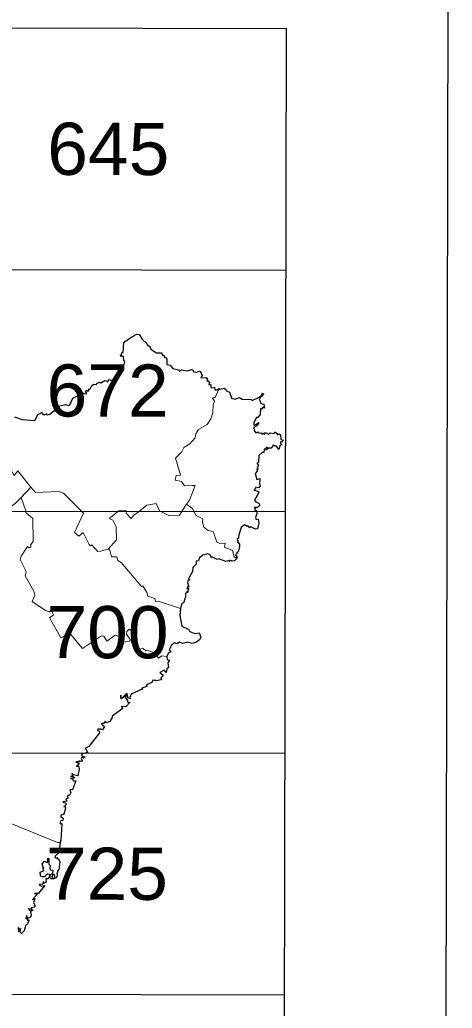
# Model space of a CAD drawing. Extents: x 483847 to 488453, y 4383581 to 4386795.
# Drawn here: x 488291.2 to 488453, y 4385556 to 4385925.5 of the extents above; entities that cross this region are included whole.
import ezdxf
from ezdxf.enums import TextEntityAlignment as Align

# ---------------------------------------------------------------- set-up
doc = ezdxf.new("R2010")
doc.units = 0
doc.header["$LTSCALE"] = 3.8
doc.header["$PDMODE"] = 32
doc.header["$PDSIZE"] = 1.9
doc.linetypes.add('DOTTED', pattern=[1.5, 0.3, -1.2])
for name, color, linetype, lineweight in [('1', 7, 'Continuous', 13), ('2', 7, 'DOTTED', 13), ('3', 7, 'Continuous', 25)]:
    doc.layers.add(name, color=color, linetype=linetype, lineweight=lineweight)

msp = doc.modelspace()

# ---------------------------------------------------------------- linework, layer by layer
at = {"layer": '1', "lineweight": 25}
for p, q in [((487975.35, 4385923.09), (488391.03, 4385922.3)), ((488390.17, 4385470.67), (488391.03, 4385922.31)), ((487975.18, 4385832.76), (488390.86, 4385831.97)), ((487836.45, 4385742.71), (488390.69, 4385741.65)), ((487836.28, 4385652.38), (488390.51, 4385651.32)), ((487836.1, 4385562.06), (488390.34, 4385561))]:
    msp.add_line(p, q, dxfattribs=at)
msp.add_lwpolyline([(483853.06, 4386794.93), (488453.05, 4386786.19), (488446.96, 4383581.19), (483846.97, 4383589.93)], close=True, dxfattribs=at)
at = {"layer": '3'}
for p, q in [((488364.27, 4385787.18), (488364.98, 4385787.18)), ((488364.98, 4385787.18), (488365.77, 4385787.65)), ((488365.77, 4385787.65), (488365.54, 4385787.18))]:
    msp.add_line(p, q, dxfattribs=at)
at = {"layer": '3', "lineweight": 13}
msp.add_line((488353.57, 4385744.47), (488351.97, 4385741.99), dxfattribs=at)
at = {"layer": '3'}
for points in [[(488330.22, 4385798.06), (488330.02, 4385799.69), (488329.33, 4385799.93), (488329.22, 4385799.57), (488328.89, 4385800.29), (488329.27, 4385800.27), (488329.54, 4385801.24), (488329.95, 4385801.17), (488330.15, 4385805.04), (488333.43, 4385807.07)], [(488333.43, 4385807.07), (488335.04, 4385807.94), (488335.96, 4385807.82), (488337.1, 4385806.06), (488338.83, 4385804.54), (488339.21, 4385803.62), (488339.81, 4385803.58), (488340.28, 4385802.35), (488342.44, 4385801.01), (488344.09, 4385800.99), (488344.78, 4385800.03), (488345.32, 4385800.06), (488345.43, 4385799.2)], [(488345.43, 4385799.2), (488346.04, 4385799.2), (488346.31, 4385798.5), (488346.26, 4385796.7), (488347.5, 4385796.38), (488348.57, 4385795.2), (488350.59, 4385794.66), (488350.99, 4385794.14), (488351.8, 4385794.65), (488353.95, 4385794.3), (488355.55, 4385794.76), (488356.03, 4385794.62), (488356.25, 4385793.91), (488357.43, 4385793.76)], [(488321.34, 4385789.9), (488321.63, 4385789.75), (488323.03, 4385790.62), (488323.77, 4385790.52), (488324.11, 4385790.02), (488324.72, 4385791.07), (488325.34, 4385790.73), (488326.19, 4385790.93), (488326.81, 4385791.84), (488327.82, 4385792.14), (488328.49, 4385792.96), (488328.24, 4385794.64), (488329.71, 4385795.43), (488330.48, 4385797.15), (488330.58, 4385797.78), (488330.22, 4385798.06)], [(488357.43, 4385793.76), (488358.8, 4385794.31), (488359.55, 4385792.56), (488359.01, 4385791.62), (488360.99, 4385791.76), (488361.48, 4385791.09), (488361.22, 4385790.48), (488361.69, 4385790.55), (488362.19, 4385789.97), (488361.96, 4385788.99), (488362.75, 4385789.13), (488362.69, 4385788.03), (488363, 4385787.9), (488364.08, 4385788.15), (488364.27, 4385787.18)], [(488316.94, 4385787.07), (488316.78, 4385786.58), (488316.35, 4385786.89), (488315.77, 4385786.58), (488316.22, 4385785.87), (488315.98, 4385785.56), (488314.88, 4385785.89), (488314.06, 4385785.07), (488313.14, 4385785.42), (488312.97, 4385784.91), (488311, 4385783.89), (488309.67, 4385781.17), (488308.45, 4385781.54)], [(488321.34, 4385789.9), (488319.95, 4385789.48), (488319.79, 4385789.09), (488318.9, 4385789.16), (488317.97, 4385788.38), (488317.41, 4385787.27), (488316.93, 4385787.48), (488316.94, 4385787.07)], [(488365.77, 4385787.65), (488366.08, 4385787.37), (488367.77, 4385787.75), (488368.52, 4385787.2)], [(488368.52, 4385787.2), (488368.64, 4385786.75), (488369.68, 4385786.35), (488370.51, 4385784.08), (488371.78, 4385783.66), (488373.5, 4385784.27), (488374.43, 4385783.74), (488377.81, 4385783.62), (488378.16, 4385783.19), (488380.58, 4385784.27), (488381.68, 4385785.1), (488381.93, 4385785.94), (488382.6, 4385785.63), (488382.05, 4385785.18), (488382.16, 4385784.89)], [(488382.16, 4385784.89), (488381.05, 4385784.28), (488380.96, 4385783.6), (488381.42, 4385782.09), (488382.6, 4385781.83), (488382.77, 4385780.37), (488382.13, 4385780.64), (488381.81, 4385780.01), (488381.33, 4385780.03), (488381.13, 4385777.91), (488380.34, 4385776.85), (488379.87, 4385776.78), (488378.83, 4385774.97), (488378.76, 4385773.78), (488379.38, 4385774.06)], [(488308.45, 4385781.54), (488305.78, 4385780.93), (488306.04, 4385780.68), (488305.14, 4385779.15), (488303.95, 4385779.2), (488302.65, 4385778.06), (488301.53, 4385777.7), (488301.32, 4385778.21), (488300.26, 4385777.68), (488299.93, 4385778.19)], [(488299.93, 4385778.19), (488299.27, 4385778.71), (488299.05, 4385778.2), (488298.03, 4385777.92), (488296.71, 4385775.58), (488292.24, 4385775.99), (488289.37, 4385776.95)], [(488379.38, 4385774.06), (488380.7, 4385774.93), (488379.92, 4385773.71), (488378.79, 4385773.07), (488378.93, 4385771.95), (488379.59, 4385771.04), (488380.6, 4385771.44), (488380.72, 4385770.95), (488381.65, 4385771.07), (488381.79, 4385770.57), (488382.36, 4385770.98), (488382.77, 4385770.59), (488383.14, 4385771.18), (488384.48, 4385770.61), (488384.97, 4385771.09), (488386.4, 4385770.9), (488386.72, 4385771.53), (488387.63, 4385770.77), (488387.54, 4385770.34), (488388.34, 4385770.77)], [(488388.34, 4385770.77), (488388.82, 4385770.4), (488388.96, 4385768.64), (488389.77, 4385768.39), (488389.45, 4385767.64), (488388.75, 4385767.78), (488388.74, 4385767.23), (488389.33, 4385766.69), (488388.51, 4385766.23), (488388.21, 4385764.83), (488387.34, 4385766.12), (488386.69, 4385766.13), (488386.16, 4385766.67), (488385.35, 4385765.43), (488384.46, 4385765.37), (488383.36, 4385764.57), (488383.53, 4385765.14)], [(488383.53, 4385765.14), (488384.25, 4385765.4), (488383.39, 4385765.78), (488383.35, 4385765.22), (488382.68, 4385765.05), (488382.57, 4385763.77), (488381.91, 4385763.73), (488380.72, 4385762.58), (488380.61, 4385759.99), (488380, 4385759.76), (488380.54, 4385759.03), (488380.12, 4385757.85), (488380.42, 4385757.39), (488379.99, 4385757.39), (488380.1, 4385756.78), (488379.34, 4385755.94)], [(488379.34, 4385755.94), (488379.91, 4385753.7), (488381.1, 4385754.01), (488380.92, 4385751.82), (488381.28, 4385751.4), (488380.75, 4385750.57), (488379.51, 4385750.81), (488379.3, 4385750.02), (488378.84, 4385749.84), (488380.72, 4385749.06), (488380.6, 4385748.49)], [(488380.6, 4385748.49), (488379.12, 4385745.88), (488379.6, 4385745.58), (488379.5, 4385745.26), (488380.72, 4385744.84), (488381.01, 4385744.12), (488380.21, 4385743.21), (488378.96, 4385743.22), (488379.3, 4385742.98), (488379.21, 4385742.21), (488379.67, 4385742.05)], [(488379.67, 4385742.05), (488379.97, 4385741.82), (488379.93, 4385740.76), (488379.43, 4385739.5), (488379.72, 4385738.72), (488380.5, 4385738.82), (488380.73, 4385737.35), (488380.22, 4385735.24), (488379.4, 4385735.05), (488377.71, 4385735.92), (488377.13, 4385735.55), (488376.66, 4385736.31), (488376.34, 4385736.06), (488375.29, 4385736.69), (488374.12, 4385735.71), (488373.19, 4385733.01)], [(488373.19, 4385733.01), (488373.04, 4385731.75), (488372.55, 4385731.34), (488373, 4385730.59), (488372.66, 4385730.3), (488373.42, 4385729.42), (488373.42, 4385728.44), (488373.03, 4385726.98), (488372.01, 4385725.5), (488372.59, 4385724.52), (488372.43, 4385724.17)], [(488359.75, 4385725.39), (488358.41, 4385724.23), (488358.09, 4385723.21), (488357.25, 4385723.08), (488357.22, 4385721.99), (488356.04, 4385720.82), (488355.91, 4385719.32), (488354.39, 4385716.55), (488354.92, 4385716.14), (488354.12, 4385715.9), (488353.97, 4385715.13), (488354.45, 4385713.47), (488354.13, 4385713.64), (488353.81, 4385712.93), (488354.59, 4385713.18), (488354.23, 4385712.75), (488354.42, 4385712.47), (488353.96, 4385712.31), (488354.29, 4385711.78), (488353.57, 4385711.69)], [(488372.43, 4385724.17), (488371.53, 4385723.23), (488370.73, 4385723.1), (488369.88, 4385723.51), (488369.7, 4385723.02), (488369.36, 4385723.26), (488368.34, 4385722.97), (488365.74, 4385723.97), (488365.16, 4385723.76), (488363.39, 4385724.61), (488362.94, 4385724.42), (488362.52, 4385725.47), (488361.56, 4385725.89), (488359.75, 4385725.39)], [(488353.57, 4385711.69), (488354.18, 4385711.38), (488353.2, 4385711.11), (488353.27, 4385709.66), (488352.82, 4385708.93), (488353.06, 4385708.76), (488352.46, 4385707.58), (488351.77, 4385707.1), (488351.43, 4385705.45)], [(488351.43, 4385705.45), (488351.13, 4385702.82), (488351.84, 4385698.86), (488354.56, 4385697.56), (488354.82, 4385696.83)], [(488354.82, 4385696.83), (488356.7, 4385696.13), (488358.42, 4385696.39), (488358.98, 4385694.75), (488358.47, 4385693.72), (488357.35, 4385692.86), (488355.7, 4385692.32), (488354.04, 4385692.85), (488352.12, 4385692.4), (488350.99, 4385692.79), (488350.09, 4385692.25)], [(488350.09, 4385692.25), (488349.13, 4385692.56), (488348.04, 4385691.75), (488347.12, 4385689.96), (488347.77, 4385689.14), (488346.95, 4385688.83), (488346.3, 4385687.53)], [(488346.3, 4385687.53), (488346.39, 4385686.42), (488347.3, 4385686.1), (488346.62, 4385685.08), (488346.93, 4385683.41), (488346.3, 4385682.89), (488346.07, 4385681.55), (488345.23, 4385682.43), (488343.71, 4385681.56), (488344.72, 4385680.64), (488344.63, 4385679.96), (488344.02, 4385679.52), (488344.25, 4385678.75), (488342.21, 4385678.42), (488341.81, 4385678.77), (488341.48, 4385678.48), (488341.03, 4385678.67), (488340.66, 4385677.76), (488338.65, 4385676.9), (488338.8, 4385676.23), (488336.93, 4385675.71), (488336.88, 4385675.42), (488337.26, 4385675.43)], [(488337.26, 4385675.43), (488332.93, 4385673.39), (488332.37, 4385672.17), (488332.64, 4385671.67), (488331.77, 4385671.91), (488331.35, 4385673.75), (488329.5, 4385672.09), (488329.11, 4385672.16), (488329.1, 4385673.07), (488328.92, 4385672.08), (488329.35, 4385671.78), (488331.19, 4385673.02), (488330.82, 4385672.09), (488331.59, 4385671.08), (488331.67, 4385670.25), (488332.57, 4385670.44), (488330.95, 4385668.73), (488329.14, 4385668.82)], [(488329.14, 4385668.82), (488329.8, 4385668.05), (488325.81, 4385665.2), (488325.88, 4385664.72), (488324.95, 4385663.24), (488323.75, 4385662.74), (488323.22, 4385663.32), (488322.86, 4385662.44), (488321.96, 4385662.48), (488321.88, 4385662.15), (488322.99, 4385661.32), (488322.17, 4385660.08), (488321.53, 4385660.26)], [(488321.53, 4385660.26), (488320.4, 4385660.31), (488320.33, 4385659.87), (488320.98, 4385659.64), (488321.11, 4385658.93), (488317.1, 4385653.85), (488315.8, 4385653.24), (488316.61, 4385651.58)], [(488316.61, 4385651.58), (488314.29, 4385651.02), (488314.58, 4385650.17), (488315.68, 4385650.02), (488315.07, 4385649.54), (488314.44, 4385649.83), (488314.24, 4385649.35), (488314.63, 4385648.61), (488314.34, 4385648.27), (488313.39, 4385648.47), (488313.61, 4385648.05), (488312.27, 4385648.17), (488313.48, 4385647.49), (488312.78, 4385646.63)], [(488312.78, 4385646.63), (488312.41, 4385646.49), (488313.33, 4385646.37), (488313.53, 4385645.34), (488312.96, 4385642.87), (488311.3, 4385643.25), (488310.79, 4385643.92), (488310.93, 4385642.91), (488310.21, 4385642.58), (488311.25, 4385642.58), (488311.88, 4385642.07), (488310.28, 4385641.77), (488310.91, 4385641.85), (488311.36, 4385641.06), (488312.17, 4385640.99), (488311.53, 4385639.02)], [(488311.53, 4385639.02), (488310.95, 4385637.6), (488309.99, 4385637.76), (488310.35, 4385636.52), (488309.83, 4385635.53), (488309.15, 4385635.49), (488309.28, 4385634.43), (488308.49, 4385634.34), (488308.9, 4385633.36), (488307.37, 4385633.16), (488308.47, 4385632.65), (488308.64, 4385632.15), (488307.73, 4385631.34), (488308.25, 4385631.4), (488308.3, 4385630.85), (488307.78, 4385628.57), (488307.25, 4385628.28)], [(488307.25, 4385628.28), (488306.88, 4385628.37), (488306.48, 4385627.67), (488307.47, 4385627.03), (488307.37, 4385626.22), (488306.6, 4385626.06), (488306.2, 4385625.27), (488306.43, 4385624.83), (488306.87, 4385625.19), (488306.93, 4385624.8), (488306.64, 4385618.82), (488306.32, 4385618.01)], [(488306.32, 4385618.01), (488305.89, 4385614.04), (488304.49, 4385612.83), (488304.43, 4385612.35), (488305.07, 4385612.05), (488305.41, 4385612.33), (488305.34, 4385611.87), (488305.87, 4385611.63), (488306.3, 4385610.72), (488305.84, 4385607.77), (488305.31, 4385607.39), (488305.5, 4385606.98)], [(488298.89, 4385606.41), (488298.94, 4385606.86), (488300.09, 4385607.35), (488300, 4385608.42), (488300.38, 4385608.51), (488300.03, 4385608.61), (488299.6, 4385609.92), (488300.5, 4385610.97), (488301.46, 4385610.44), (488301.79, 4385610.87), (488301.78, 4385612.13), (488302.17, 4385611.95), (488302.07, 4385609.85), (488302.67, 4385609.3), (488302.48, 4385608.18), (488302.65, 4385607.72), (488303.56, 4385607.58), (488303.53, 4385606.41)], [(488298.89, 4385606.41), (488298.87, 4385605.53), (488299.63, 4385605.22), (488300.66, 4385605.2), (488301.67, 4385606.25), (488302.4, 4385606.1), (488302.65, 4385605.66), (488301.71, 4385604.38), (488301.01, 4385604.42), (488301.18, 4385603.08), (488300.53, 4385602.81), (488299.96, 4385603.4), (488299.98, 4385602.66), (488299.6, 4385602.3), (488298.65, 4385602.38), (488298.62, 4385602.01), (488299.35, 4385601.66), (488300.61, 4385601.92), (488298.62, 4385599.5)], [(488303.53, 4385606.41), (488303.42, 4385604.7), (488303.76, 4385604.42), (488304.99, 4385604.92), (488305.4, 4385605.64), (488305.28, 4385606.42)], [(488305.5, 4385606.98), (488305.2, 4385606.89), (488305.28, 4385606.42)], [(488298.62, 4385599.5), (488298.3, 4385598.86), (488296.76, 4385598.92), (488297.75, 4385598.57), (488296.07, 4385596.63), (488296.86, 4385597.01), (488296.44, 4385595.5), (488296.98, 4385594.16), (488296.62, 4385593.73), (488295.54, 4385593.53), (488295.6, 4385593.12), (488295.1, 4385592.92), (488294.35, 4385593.26), (488295.12, 4385592.4), (488296.04, 4385592.95), (488296.18, 4385592.68), (488295.25, 4385591.98), (488295.51, 4385590.8), (488295.26, 4385590.09), (488294.15, 4385589.6), (488294.09, 4385589.86)], [(488294.09, 4385589.86), (488293.78, 4385590.7), (488293.78, 4385589.85), (488293.38, 4385589.68), (488293.84, 4385589.53), (488294.09, 4385588.79), (488294.39, 4385589.15), (488294.61, 4385588.84), (488294.12, 4385587.5), (488293.4, 4385586.84), (488292.94, 4385584.96), (488291.84, 4385583.89), (488291.43, 4385584.4), (488291.64, 4385585.83), (488291.25, 4385585.25), (488290.84, 4385586.02), (488290.56, 4385585.9), (488290.91, 4385584.89), (488290.67, 4385584.48)]]:
    msp.add_lwpolyline(points, dxfattribs=at)
at = {"layer": '3', "lineweight": 13}
for points in [[(488365.54, 4385787.18), (488364.31, 4385784.3), (488363.4, 4385784.17), (488364.16, 4385782.95), (488363.56, 4385781.58), (488363.43, 4385778.58), (488362.77, 4385776.39), (488361.39, 4385774.16), (488358.14, 4385772.31), (488357.13, 4385770.73), (488356.83, 4385769.28), (488354.89, 4385766.96), (488352.66, 4385765.61), (488351.82, 4385763.85), (488349.57, 4385761.66), (488351.41, 4385755.27), (488349.79, 4385755.21), (488349.38, 4385753.38), (488351.8, 4385752.86), (488352.85, 4385751.27), (488355.77, 4385751.42)], [(488284.6, 4385761.41), (488285.27, 4385760.6), (488285.14, 4385759.17), (488284.57, 4385758.65), (488287.69, 4385757.73), (488289.13, 4385755.16), (488290.47, 4385756.9), (488295.44, 4385750.84)], [(488295.44, 4385750.84), (488291.72, 4385746.88), (488293.53, 4385741.9)], [(488295.44, 4385750.84), (488297.15, 4385748.8), (488305.83, 4385749.21), (488307.67, 4385748.53), (488314.28, 4385741.91)], [(488355.77, 4385751.42), (488356.87, 4385751.37), (488354.72, 4385745.93), (488353.57, 4385744.47)], [(488291.72, 4385746.88), (488289.56, 4385744.65), (488286.02, 4385742.23), (488278.18, 4385748.08), (488276.81, 4385744.8), (488276.4, 4385742.39), (488275.8, 4385741.88)], [(488336.15, 4385741.95), (488338.74, 4385744.1), (488342.24, 4385744.69), (488343.53, 4385741.96)], [(488353.57, 4385744.47), (488355.83, 4385742.82), (488356.26, 4385742)], [(488293.53, 4385741.9), (488293.55, 4385741.34), (488296.17, 4385739.08), (488296.21, 4385730.46), (488295.44, 4385729.38), (488295.35, 4385728.5), (488294.73, 4385728.12), (488294.19, 4385728.57), (488291.8, 4385725.05), (488291.39, 4385723.76), (488293.64, 4385719.28), (488293.22, 4385717.69), (488296.55, 4385711.94), (488296.92, 4385710.42), (488295.95, 4385708.07), (488300.9, 4385704.64), (488302.39, 4385704.21), (488302.96, 4385704.87), (488303.84, 4385703.09), (488302.39, 4385701.92), (488305.31, 4385696.74)], [(488314.28, 4385741.91), (488315.12, 4385741.11), (488311.71, 4385733.8), (488313.29, 4385732.52), (488315.02, 4385733.78), (488317.16, 4385729.32), (488317.66, 4385728.91), (488318.2, 4385729.17), (488320.43, 4385726.7), (488321.43, 4385726.92)], [(488328.31, 4385741.92), (488324.67, 4385739.08), (488326.09, 4385738.42), (488327.26, 4385735.94), (488327.43, 4385731.12), (488324.32, 4385727.62), (488321.43, 4385726.92)], [(488328.31, 4385741.92), (488328.87, 4385742.23), (488331.16, 4385741.94)], [(488331.16, 4385741.94), (488331.11, 4385741.12), (488332.93, 4385739.1), (488333.77, 4385740.19), (488336.15, 4385741.95)], [(488343.53, 4385741.96), (488347.02, 4385740.14), (488350.97, 4385740.38), (488351.97, 4385741.99)], [(488356.26, 4385742), (488357.29, 4385740.24), (488359.72, 4385738.92), (488359.56, 4385737.75), (488360.07, 4385735.87), (488361.79, 4385734.61), (488363.59, 4385734.17), (488364.92, 4385730.29), (488366.1, 4385729.72), (488368.04, 4385729.85), (488367.82, 4385728.32), (488370.88, 4385727.12), (488371.44, 4385724.78), (488372.43, 4385724.17)], [(488324.32, 4385727.62), (488324.98, 4385727.28), (488325.53, 4385724.77), (488327.51, 4385724.72), (488327.94, 4385723.4), (488329.24, 4385722.68), (488336.81, 4385713.71), (488337.32, 4385713.89), (488338.75, 4385711.47), (488339.16, 4385709.99), (488341.79, 4385709.17), (488341.99, 4385708.06), (488342.99, 4385708.13), (488351.43, 4385705.45)], [(488305.31, 4385696.74), (488306.61, 4385694.49), (488309.24, 4385695.65), (488309.64, 4385696.59), (488314.66, 4385690.45), (488321.48, 4385694.98)], [(488331.34, 4385696.78), (488331.15, 4385695.89), (488332.58, 4385693.9), (488332.37, 4385693.21), (488330.08, 4385692.9), (488328.33, 4385695), (488327, 4385695.41), (488323.79, 4385693.23), (488322.71, 4385695.08), (488321.9, 4385695.27), (488321.48, 4385694.98)], [(488331.34, 4385696.78), (488332.21, 4385697.7), (488333.49, 4385696.78)], [(488333.49, 4385696.78), (488334.51, 4385694.5), (488332.98, 4385693.49), (488333.15, 4385692.57), (488333.72, 4385692.09), (488335.16, 4385692.9), (488335.51, 4385690.26), (488337.47, 4385690.51), (488338.44, 4385689.6), (488339.39, 4385689.73), (488341.97, 4385688.62), (488343.16, 4385686.87), (488344.38, 4385687.72), (488346.3, 4385687.53)], [(488271.35, 4385651.56), (488271.67, 4385651.26), (488272.21, 4385651.43), (488272.45, 4385647.98), (488273.02, 4385646.18), (488275.13, 4385642.37), (488281.06, 4385637.53), (488276.54, 4385631.14), (488284.34, 4385626.54), (488305.36, 4385618.01), (488306.32, 4385618.01)]]:
    msp.add_lwpolyline(points, dxfattribs=at)
at = {"layer": '3'}
msp.add_point((488303.34, 4385605.29), dxfattribs=at)

# ---------------------------------------------------------------- texts
at = {"layer": '2', "width": 1.05}
for s, p in [('645', (488324.35, 4385867.5)), ('672', (488324.1, 4385777.17)), ('700', (488324.06, 4385686.84)), ('725', (488323.83, 4385596.53))]:
    msp.add_text(s, height=19.5, rotation=359.891, dxfattribs=at).set_placement(p, align=Align.CENTER)

doc.saveas('drawing.dxf')
